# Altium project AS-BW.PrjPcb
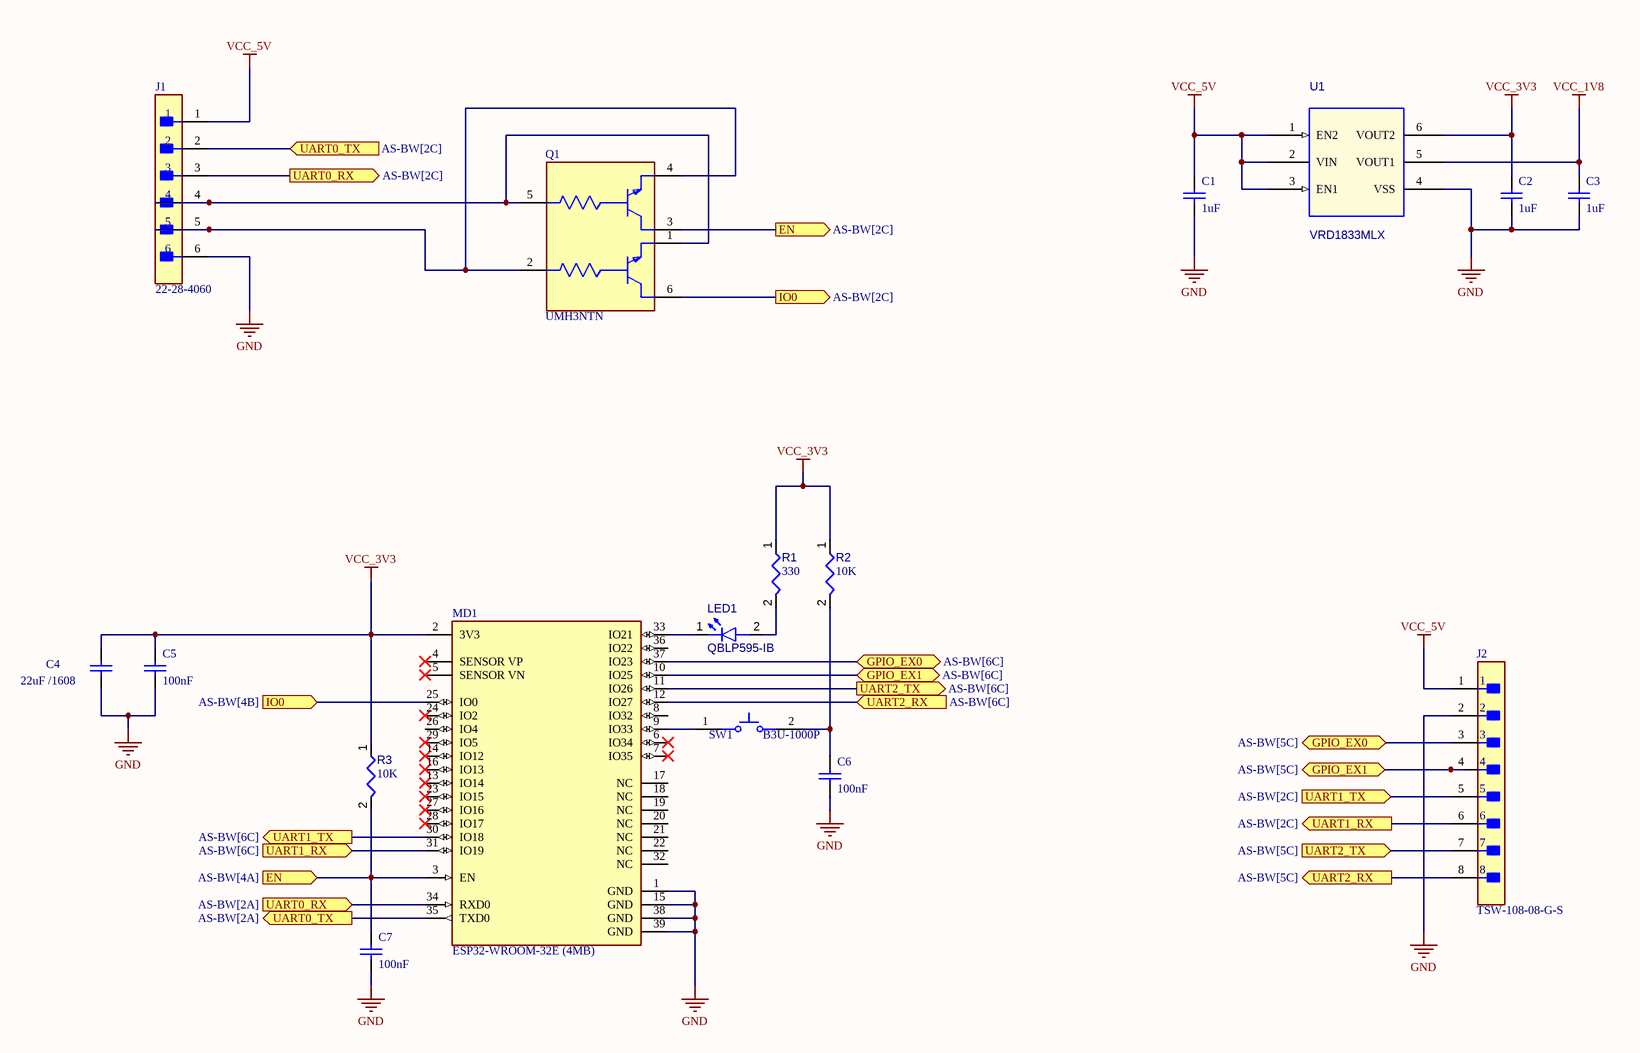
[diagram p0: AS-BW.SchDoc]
1 sheet, 17 parts. Net scope: flat (ports and power ports of the same name join across sheets).
Board file: AS-BW.PcbDoc

## Sheet AS-BW.SchDoc
size A3; SheetNumber: 1; SheetTotal: 1; SPICEModelCacheZHFQSIYZ: <root> / <DocumentId>ZHFQSIYZ</DocumentId> / <CacheFrame Number="0"> / <Model Name="cap" Kind="MDL"> / <Text>*Default semiconductor capacitor / .MODEL CAP C()</Text> / </Model> / </CacheFrame> / </root>

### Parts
C1  value 1uF  [CAP 0402/1005]  (hidden comment: Cap Semi)
C2  value 1uF  [CAP 0402/1005]  (hidden comment: Cap Semi)
C3  value 1uF  [CAP 0402/1005]  (hidden comment: Cap Semi)
C4  value 22uF /1608  [CAP 0603/1608]  (hidden comment: Cap Semi)
C5  value 100nF  [CAP 0402/1005]  (hidden comment: Cap Semi)
C6  value 100nF  [CAP 0402/1005]  (hidden comment: Cap Semi)
C7  value 100nF  [CAP 0402/1005]  (hidden comment: Cap Semi)
J1  22-28-4060  [FP-22-28-4060-MFG]
J2  TSW-108-08-G-S  [FP-TSW-108-08-G-S-MFG]
LED1  QBLP595-IB  [LED 0402/1005 GREEN -21]
MD1  ESP32-WROOM-32E (4MB)  [FP-ESP32-WROOM-32E_4MB-MFG]
Q1  UMH3NTN  [FP-UMT6-IPC_C]
R1  value 330  [RES 0402/1005]  (hidden comment: Resistor 10k +/-1% 0805 125 mW)
R2  value 10K  [RES 0402/1005]  (hidden comment: Resistor 10k +/-1% 0805 125 mW)
R3  value 10K  [RES 0402/1005]  (hidden comment: Resistor 10k +/-1% 0805 125 mW)
SW1  B3U-1000P  [B3U-1000P]
U1  VRD1833MLX  [LLP-6 / L2.0-W1.8-P0.50-BL-EP]

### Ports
EN (in, see AS-BW[4A]), EN (out, see AS-BW[2C]), GPIO_EX0 (bidir, see AS-BW[5C]), GPIO_EX0 (bidir, see AS-BW[6C]), GPIO_EX1 (bidir, see AS-BW[5C]), GPIO_EX1 (bidir, see AS-BW[6C]), IO0 (in, see AS-BW[4B]), IO0 (out, see AS-BW[2C]), UART0_RX (in, see AS-BW[2A]), UART0_RX (out, see AS-BW[2C]), UART0_TX (in, see AS-BW[2C]), UART0_TX (out, see AS-BW[2A]), UART1_RX (in, see AS-BW[6C]), UART1_RX (out, see AS-BW[2C]), UART1_TX (in, see AS-BW[2C]), UART1_TX (out, see AS-BW[6C]), UART2_RX (in, see AS-BW[6C]), UART2_RX (out, see AS-BW[5C]), UART2_TX (in, see AS-BW[5C]), UART2_TX (out, see AS-BW[6C])

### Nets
GND: C1.1 C2.1 C3.1 C4.1 C5.1 C6.1 C7.1 J1.6 J2.2 MD1.1(GND) MD1.15(GND) MD1.38(GND) MD1.39(GND) U1.4(VSS)
VCC_1V8: C3.2 U1.5(VOUT1)
VCC_3V3: C2.2 C4.2 C5.2 MD1.2(3V3) R1.1 R2.1 R3.1 U1.6(VOUT2)
VCC_5V: C1.2 J1.1 J2.1 U1.1(EN2) U1.2(VIN) U1.3(EN1)
NetC6_2: C6.2 R2.2 SW1.2
NetC7_2: C7.2 MD1.3(EN) Q1.3(C) R3.2 ; port EN
NetJ1_2: J1.2 MD1.35(TXD0) ; port UART0_TX
NetJ1_3: J1.3 MD1.34(RXD0) ; port UART0_RX
NetJ1_4: J1.4 Q1.1(E) Q1.5(B)
NetJ1_5: J1.5 Q1.2(B) Q1.4(E)
NetJ2_3: J2.3 MD1.37(IO23) ; port GPIO_EX0
NetJ2_4: J2.4 MD1.10(IO25) ; port GPIO_EX1
NetJ2_5: J2.5 MD1.30(IO18) ; port UART1_TX
NetJ2_6: J2.6 MD1.31(IO19) ; port UART1_RX
NetJ2_7: J2.7 MD1.11(IO26) ; port UART2_TX
NetJ2_8: J2.8 MD1.12(IO27) ; port UART2_RX
NetLED1_1: LED1.1(K) MD1.33(IO21)
NetLED1_2: LED1.2(A) R1.2
NetMD1_9: MD1.9(IO33) SW1.1
NetMD1_25: MD1.25(IO0) Q1.6(C) ; port IO0

Not connected (* = marked no-connect by the designer): MD1 4(SENSOR_VP)* 5(SENSOR_VN)* 6(IO34)* 7(IO35)* 8(IO32) 13(IO14)* 14(IO12)* 16(IO13)* 17(NC) 18(NC) 19(NC) 20(NC) 21(NC) 22(NC) 23(IO15)* 24(IO2)* 26(IO4) 27(IO16)* 28(IO17)* 29(IO5)* 32(NC) 36(IO22)

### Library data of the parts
C1-C7 = Cap Semi: Capacitor (Semiconductor SIM Model)
J1 = CMP-04776-000763-1: CONN HEADER VERT 6POS 2.54MM; Voltage Rating: 250V; Current Rating: 4A; Number of Contacts: 6; Max Voltage Rating (DC): 250.25kV; Gender: Male; Contact Resistance: 20mR; Connector Type: Male Pin
J2 = CMP-02766-000001-1: CONN HEADER VERT 8POS 2.54MM; Manufacturer: Samtec; Number Of Contacts: 8; Conn Orientation: Straight; Conn Gender: Male
LED1 = LED-KA-2: Chip LED 0402, Blue, 0.02 A, 3.1 to 3.7 V, -40 to 80 degC, 2-Pin SMD, RoHS, Tape and Reel
MD1 = CMP-194065-000026-1: RX TXRX MOD WIFI TRACE ANT SMD
Q1 = CMP-08979-000010-1: TRANS 2NPN PREBIAS 0.15W UMT6; Transition Frequency: 250MHz; Collector Base Voltage (VCBO): 50V; Element Configuration: Dual; Emitter Base Voltage (VEBO): 5V; Max Collector Current: 100mA; Polarity: NPN; hFE Min: 100; Max Power Dissipation: 150mW; Collector-emitter Voltage-Max: 300mV
R1-R3 = RES-2: Chip Resistor, 10 KOhm, +/- 1%, 125 mW, -55 to 155 degC, 0805 (2012 Metric); Power: 125mW; Voltage Rating: 150V
SW1 = SW-SPST-NO-2: Tactile Switch, SPST-NO, 0.05 A, 12 V, -25 to 70 degC, 2-Pin SMD, RoHS, Tape and Reel; Manufacturer: Omron Electronic Components; IP Rating: IP40; Current Rating: 50mA; Max Contact Resistance: 100mohm; Operating Force: 153gf; Throw Configuration: SPST; Resistance: 0.1Ohm; Max Voltage Rating (DC): 12V
U1 = VRD1833MLX: Part Reference: U1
